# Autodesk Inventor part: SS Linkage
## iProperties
Shininess: 64.0
Length Units: 11272
Angle Units: 11279
Time Units: 11290
Mass Units: 11286
Length Display Precision: 3
Angle Display Precision: 2
Compacted: True
Part Number: SS Linkage
Document SubType Name: Modeling
Created: 2004-04
Designer: jpittman
Manufacturer: Standard
Standards Organization: Custom
Density: 0.0
Volumn: 0.0
Area: 0.0
PropertySet Name: Model Information
Control State: 0
Master: False
Checked Out: False
Author: jpittman
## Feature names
1. Extrusion1
2. Extrusion2
3. Hole1
4. Hole2
